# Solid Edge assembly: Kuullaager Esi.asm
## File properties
Author: Türk
Template: Iso Assembly.asm
Last saved by: Türk
Revision: 3
Application: Solid Edge
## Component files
lss2.par
el2.par
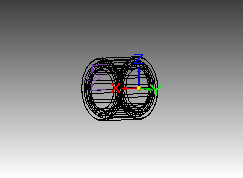
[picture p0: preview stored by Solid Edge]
